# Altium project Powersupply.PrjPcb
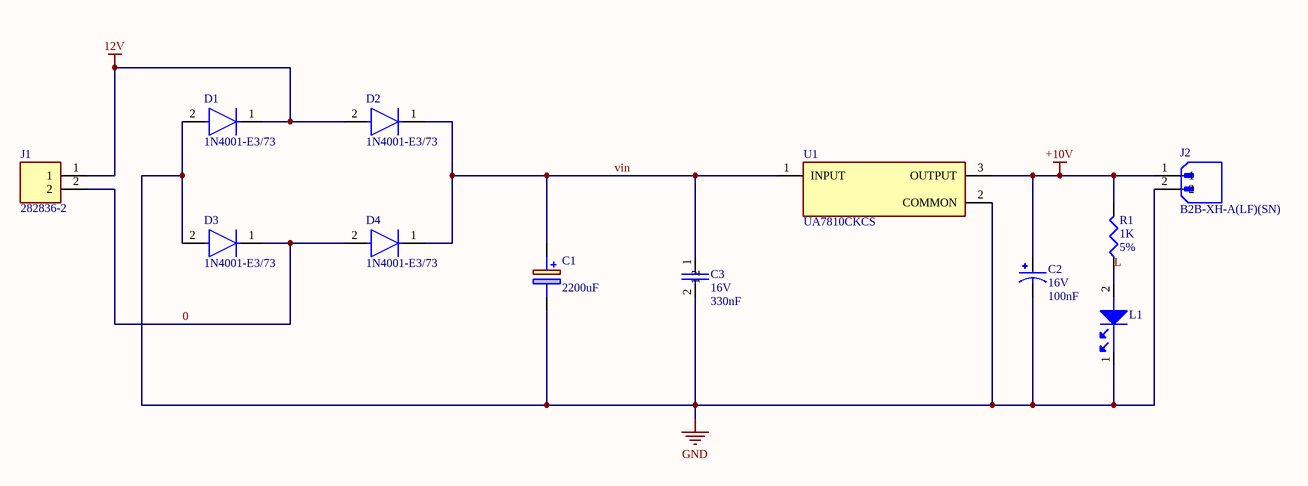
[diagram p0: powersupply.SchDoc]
1 sheet, 12 parts. Net scope: global (net labels, ports and power ports of the same name join across sheets).
Board file: powersupply.PcbDoc

## Sheet powersupply.SchDoc
size A; SheetNumber: 1; SheetTotal: 1

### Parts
C1  value 2200uF  [CAPPRD500W60D1275H2200]  (hidden comment: MAL217255222E3)
C2  Voltage: 16V  [100nF_Capacitor - duplicate]  (hidden comment: 100nF)
C3  Voltage: 16V  [330nF_Capacitor - duplicate1]  (hidden comment: 330nF)
D1  1N4001-E3/73  [FP-1N4001-E3-73-MFG]
D2  1N4001-E3/73  [FP-1N4001-E3-73-MFG]
D3  1N4001-E3/73  [FP-1N4001-E3-73-MFG]
D4  1N4001-E3/73  [FP-1N4001-E3-73-MFG]
J1  282836-2  [TE_282836-2]
J2  B2B-XH-A(LF)(SN)  [JST_B2B-XH-A(LF)(SN)]
L1  WP7113SRD/J4  [LEDRD254W57D500H1070]  (value not drawn)
R1  Resistance: 1K  Tolerance: 5%  [Resister]  (hidden comment: CFM12JT1K00)
U1  UA7810CKCS  [FP-KCS0003B-MFG]

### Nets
12V: D1.1(C) D2.2(A) J1.1
+10V: C2.1 J2.1 R1.2 U1.3(OUTPUT)
GND: C1.2(-) C2.2 C3.2 D1.2(A) D3.2(A) J2.2 L1.1 U1.2(COMMON)
0: D3.1(C) D4.2(A) J1.2
L: L1.2 R1.1
vin: C1.1(+) C3.1 D2.1(C) D4.1(C) U1.1(INPUT)

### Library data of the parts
C1 = MAL217255222E3: Aluminum Electrolytic Capacitors Radial Miniature, Low Impedance, Automotive Grade; Manufacturer_Name: Vishay; Geometry.Height: 22mm
C2 = 100nF: Aluminum Electrolytic Capacitor, Polarized, Aluminum (wet), 50V, 20% +Tol, 20% -Tol, 100nF, Through Hole Mount; Manufacturer: Panasonic; Manufacturer Part Number: EEA-GA1C100; Manufacturer Series: GA; Dielectric Material: Aluminium; Leakage Current: 3uA; Ripple Current: 30mA; Tan Delta: 0.18
C3 = 330nF: Ceramic Capacitor, Ceramic, 16V, 10% +Tol, 10% -Tol, SL0, 120ppm/Cel TC, 330nF, Through Hole Mount; Manufacturer: Vishay BCcomponents; Manufacturer Part Number: S220K25SL0N63L6R
D1-D4 = CMP-02540-000001-1: DIODE GEN PURP 50V 1A DO204AL; Manufacturer: Vishay; Max Surge Forward Current: 30A; Value: 15pF; Peak Reverse Current: 5uA; Max Junction Temp: +150°C
J1 = 282836-2: Terminal Block Connector Wire Receptacle 2 5 mm 30-16 AWG Green 13.5 A 300 V ¦ TE Connectivity 282836-2
J2 = B2B-XH-A(LF)(SN): Connector Header Through Hole 2 position 0.098 (2.50mm); MF: JST Sales America Inc.
L1 = WP7113SRD/J4: LED Uni-Color SB. Red 660nm 2-Pin T-1 3/4 Bulk; Manufacturer: Kingbright
R1 = CFM12JT1K00: Fixed Resistor, Carbon Film, 0.5W, 1000ohm, 350V, 5% +/-Tol, -400,0ppm/Cel, Through Hole Mount; Manufacturer: Stackpole Electronics; Power: 500mW; Rated Temperature: 70°C; Value: 1kR; Temperature Coefficient: 400ppm/°C; Lead Diameter: 0.55mm; Lead Length: 28mm; Package Diameter: 2.3mm; Package Length: 6mm
U1 = CMP-04917-000126-1: IC REG LINEAR 10V 1.5A TO220-3; Output Type: Fixed; Number of Regulators: 1; Dropout Voltage: 2V; Min Output Voltage: 9.5V; Power Supply Rejection Ratio (PSRR): 71dB; Min Input Voltage: 12.5V; Quiescent Current: 8mA; Polarity: Positive; Max Output Voltage: 10.5V; Max Input Voltage: 28V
